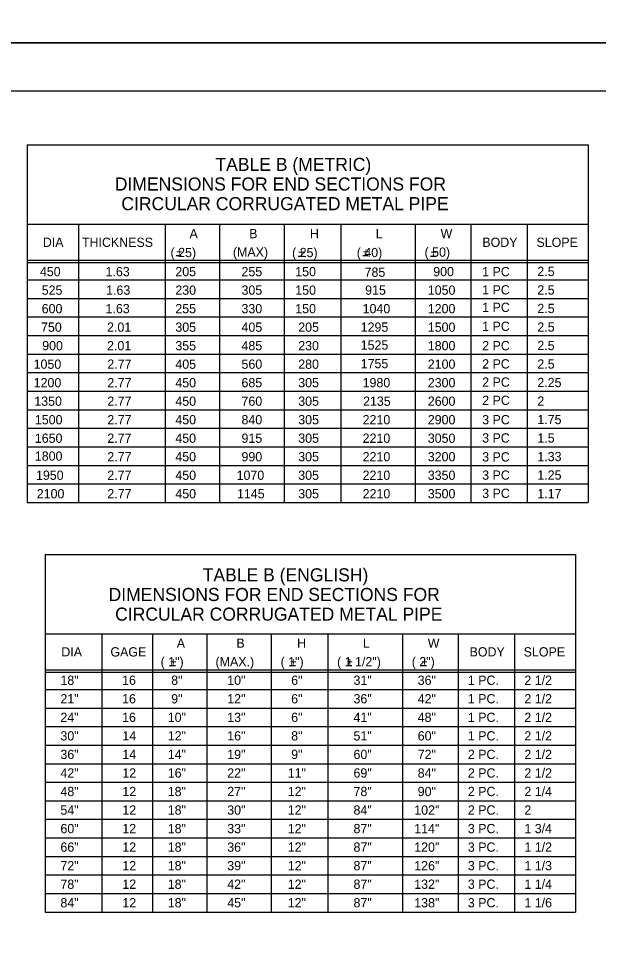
# Model space of a CAD drawing. Extents: x -17 to 888, y -473 to 715.
# Drawn here: x 265 to 444.9, y -161.9 to 128.4 of the extents above; entities that cross this region are included whole.
import ezdxf

# ---------------------------------------------------------------- set-up
doc = ezdxf.new("R2010")
doc.units = 0
for name, color, linetype in [('1', 7, 'Continuous'), ('2', 7, 'Continuous'), ('3', 7, 'Continuous'), ('PLT-BNDY', 7, 'Continuous')]:
    doc.layers.add(name, color=color, linetype=linetype)

msp = doc.modelspace()

# ---------------------------------------------------------------- linework, layer by layer
at = {"layer": '1'}
msp.add_lwpolyline([(808.79, -458.11), (808.79, 105.89), (22.79, 105.89), (22.79, -458.11), (808.79, -458.11), (808.79, -431.75), (608.79, -431.75), (608.79, -367.07), (808.79, -367.07), (808.79, -338.11), (608.79, -338.11), (608.79, -458.11), (687.6, -458.11), (687.6, -431.75), (687.6, -458.11), (764.6, -458.11), (764.6, -431.75), (764.6, -444.07), (808.79, -444.07)], dxfattribs=at)
at = {"layer": '2'}
for p, q in [((313.86, 54.8), (315.47, 54.8)), ((351.73, 54.67), (353.33, 54.67)), ((371.79, 54.8), (373.39, 54.8)), ((392.8, 54.67), (394.4, 54.67)), ((312.05, -72.55), (313.65, -72.55)), ((349.28, -72.55), (350.88, -72.55)), ((366.81, -72.55), (368.41, -72.55)), ((389.97, -72.55), (391.57, -72.55))]:
    msp.add_line(p, q, dxfattribs=at)
at = {"layer": '3'}
for p, q in [((267.68, 89.16), (267.68, -21.87)), ((267.68, 89.16), (441.73, 89.16)), ((441.73, 89.16), (441.73, -21.87)), ((267.68, 64.52), (441.73, 64.52)), ((277.2, 64.52), (294.77, 64.52)), ((283.61, 64.52), (283.61, -21.87)), ((294.77, 64.52), (310.45, 64.52)), ((310.45, 64.52), (310.45, -21.87)), ((327.35, 64.52), (327.35, -21.87)), ((347.35, 64.52), (347.35, -21.87)), ((364.92, 64.52), (364.92, -21.87)), ((388.03, 64.52), (388.03, -21.87)), ((405.34, 64.52), (405.34, -21.87)), ((405.34, 64.52), (422.77, 64.52)), ((422.77, 64.52), (422.77, -21.87)), ((422.77, 64.52), (441.73, 64.52)), ((441.73, 58.76), (441.73, 1.17)), ((267.68, 53.35), (441.73, 53.35)), ((267.68, 52.66), (441.73, 52.66)), ((267.68, 47.24), (441.73, 47.24)), ((267.68, 41.49), (441.73, 41.49)), ((267.68, 35.73), (441.73, 35.73)), ((267.68, 29.97), (441.73, 29.97)), ((267.68, 24.21), (441.73, 24.21)), ((267.68, 18.45), (441.73, 18.45)), ((267.68, 12.69), (441.73, 12.69)), ((267.68, 6.93), (441.73, 6.93)), ((267.68, 1.17), (441.73, 1.17)), ((267.68, -4.59), (441.73, -4.59)), ((267.68, -10.35), (441.73, -10.35)), ((267.68, -16.11), (441.73, -16.11)), ((267.68, -21.87), (441.73, -21.87)), ((277.2, -21.87), (277.2, -21.87)), ((273.23, -38.07), (273.23, -149.1)), ((273.23, -38.07), (437.77, -38.07)), ((437.77, -38.07), (437.77, -149.1)), ((273.23, -62.7), (437.77, -62.7)), ((273.23, -62.7), (273.23, -73.88)), ((273.23, -62.7), (290.8, -62.7)), ((290.8, -62.7), (290.8, -149.1)), ((290.8, -62.7), (306.48, -62.7)), ((306.48, -62.7), (306.48, -149.1)), ((323.38, -62.7), (323.38, -149.1)), ((343.38, -62.7), (343.38, -149.1)), ((360.95, -62.7), (360.95, -149.1)), ((384.07, -62.7), (384.07, -149.1)), ((401.37, -62.7), (401.37, -149.1)), ((401.37, -62.7), (418.81, -62.7)), ((418.81, -62.7), (418.81, -149.1)), ((418.81, -62.7), (437.77, -62.7)), ((437.77, -68.46), (437.77, -126.06)), ((273.23, -73.88), (437.77, -73.88)), ((273.23, -74.56), (437.77, -74.56)), ((273.23, -79.98), (437.77, -79.98)), ((273.23, -85.74), (437.77, -85.74)), ((273.23, -85.74), (273.23, -91.5)), ((273.23, -91.5), (437.77, -91.5)), ((273.23, -97.26), (437.77, -97.26)), ((273.23, -103.02), (437.77, -103.02)), ((273.23, -108.78), (437.77, -108.78)), ((273.23, -114.54), (437.77, -114.54)), ((273.23, -120.3), (437.77, -120.3)), ((273.23, -126.06), (437.77, -126.06)), ((273.23, -131.82), (437.77, -131.82)), ((273.23, -137.58), (437.77, -137.58)), ((273.23, -143.34), (437.77, -143.34)), ((273.23, -149.1), (437.77, -149.1)), ((273.23, -149.1), (273.23, -149.1)), ((437.77, -149.1), (437.77, -149.1))]:
    msp.add_line(p, q, dxfattribs=at)
at = {"layer": 'PLT-BNDY'}
for points in [[(-17.21, 714.89), (823.79, 714.89), (823.79, 120.89), (-17.21, 120.89)], [(-17.21, 120.89), (823.79, 120.89), (823.79, -473.11), (-17.21, -473.11)]]:
    msp.add_lwpolyline(points, close=True, dxfattribs=at)

# ---------------------------------------------------------------- texts
at = {"layer": '2'}
for p in [(313.86, 54.78), (351.72, 54.65), (371.78, 54.78), (392.79, 54.65), (312.04, -72.57), (349.27, -72.57), (366.8, -72.57), (389.96, -72.57)]:
    msp.add_text('+', height=2.47, dxfattribs=at).set_placement(p)
at = {"layer": '3'}
for s, height, p in [('TABLE B (METRIC)', 4.0685, (326.04, 81.1)), ('DIMENSIONS FOR END SECTIONS FOR', 4.0685, (294.82, 75)), ('CIRCULAR CORRUGATED METAL PIPE', 4.0682, (296.86, 68.9)), ('A', 2.88, (318.02, 60.2)), ('B', 2.88, (336.52, 60.2)), ('H', 2.88, (355.37, 60.2)), ('L', 2.88, (375.78, 60.2)), ('W', 2.88, (395.92, 60.2)), ('DIA', 2.88, (272.5, 57.5)), ('THICKNESS', 2.88, (284.64, 57.5)), ('BODY', 2.88, (408.87, 57.5)), ('SLOPE', 2.88, (425.67, 57.5)), ('( 25)', 2.88, (312.13, 54.32)), ('(MAX)', 2.88, (331.48, 54.44)), ('( 25)', 2.88, (349.84, 54.32)), ('( 40)', 2.88, (369.9, 54.32)), ('( 50)', 2.88, (390.94, 54.44)), ('450 ', 2.88, (271.6, 48.39)), ('1.63', 2.88, (291.96, 48.39)), ('205 ', 2.88, (313.62, 48.39)), ('255 ', 2.88, (334.14, 48.39)), ('150 ', 2.88, (350.83, 48.39)), ('785 ', 2.88, (372.33, 48.21)), ('900 ', 2.88, (393.64, 48.39)), ('1 PC ', 2.88, (408.83, 48.39)), ('2.5  ', 2.88, (425.94, 48.44)), ('525 ', 2.88, (272.15, 42.64)), ('1.63', 2.88, (292.14, 42.64)), ('230 ', 2.88, (313.62, 42.64)), ('305 ', 2.88, (334.14, 42.64)), ('150 ', 2.88, (350.83, 42.64)), ('915 ', 2.88, (372.51, 42.64)), ('1050', 2.88, (391.95, 42.64)), ('1 PC ', 2.88, (408.83, 42.73)), ('2.5  ', 2.88, (425.94, 42.69)), ('600 ', 2.88, (272.15, 36.89)), ('1.63', 2.88, (291.96, 36.89)), ('255 ', 2.88, (313.62, 36.89)), ('330 ', 2.88, (334.14, 36.89)), ('150 ', 2.88, (350.83, 36.89)), ('1040', 2.88, (371.73, 36.89)), ('1200', 2.88, (391.95, 36.89)), ('1 PC ', 2.88, (408.83, 37.3)), ('2.5  ', 2.88, (425.94, 36.94)), ('750 ', 2.88, (271.94, 31.14)), ('2.01', 2.88, (292.43, 31.14)), ('305 ', 2.88, (313.62, 31.14)), ('405 ', 2.88, (334.14, 31.14)), ('205 ', 2.88, (351.75, 31.14)), ('1295', 2.88, (371.13, 31.14)), ('1500', 2.88, (391.95, 31.14)), ('1 PC ', 2.88, (408.83, 31.41)), ('2.5  ', 2.88, (425.94, 31.19)), ('900 ', 2.88, (272.31, 25.39)), ('2.01', 2.88, (292.43, 25.39)), ('355 ', 2.88, (313.62, 25.39)), ('485 ', 2.88, (334.14, 25.39)), ('230 ', 2.88, (351.75, 25.39)), ('1525', 2.88, (371.13, 25.57)), ('1800', 2.88, (391.95, 25.39)), ('2 PC ', 2.88, (408.83, 25.39)), ('2.5  ', 2.88, (425.94, 25.44)), ('1050', 2.88, (269.64, 19.64)), ('2.77', 2.88, (292.51, 19.64)), ('405 ', 2.88, (313.62, 19.64)), ('560 ', 2.88, (334.14, 19.64)), ('280 ', 2.88, (351.75, 19.64)), ('1755', 2.88, (371.13, 19.82)), ('2100', 2.88, (391.95, 19.64)), ('2 PC ', 2.88, (408.83, 19.73)), ('2.5  ', 2.88, (425.94, 19.69)), ('1200', 2.88, (269.66, 13.89)), ('2.77', 2.88, (292.51, 13.89)), ('450 ', 2.88, (313.62, 13.89)), ('685 ', 2.88, (334.14, 13.89)), ('305 ', 2.88, (351.75, 13.89)), ('1980', 2.88, (371.73, 13.89)), ('2300', 2.88, (391.95, 13.89)), ('2 PC ', 2.88, (408.83, 14.07)), ('2.25 ', 2.88, (425.94, 13.94)), ('1350', 2.88, (269.85, 8.14)), ('2.77', 2.88, (292.51, 8.14)), ('450 ', 2.88, (313.62, 8.14)), ('760 ', 2.88, (334.14, 8.14)), ('305 ', 2.88, (351.75, 8.14)), ('2135', 2.88, (371.86, 8.14)), ('2600', 2.88, (391.95, 8.14)), ('2 PC ', 2.88, (408.83, 8.41)), ('2    ', 2.88, (425.94, 8.19)), ('1500', 2.88, (270.03, 2.39)), ('2.77', 2.88, (292.51, 2.39)), ('450 ', 2.88, (313.62, 2.39)), ('840 ', 2.88, (334.14, 2.39)), ('305 ', 2.88, (351.75, 2.39)), ('2210', 2.88, (371.73, 2.39)), ('2900', 2.88, (391.95, 2.39)), ('3 PC ', 2.88, (408.83, 2.39)), ('1.75 ', 2.88, (425.94, 2.44)), ('1650', 2.88, (270.02, -3.36)), ('2.77', 2.88, (292.51, -3.36)), ('450 ', 2.88, (313.62, -3.36)), ('915 ', 2.88, (334.14, -3.36)), ('305 ', 2.88, (351.75, -3.36)), ('2210', 2.88, (371.73, -3.36)), ('3050', 2.88, (391.95, -3.36)), ('3 PC ', 2.88, (408.83, -3.27)), ('1.5  ', 2.88, (425.94, -3.31)), ('1800', 2.88, (270.02, -8.92)), ('2.77', 2.88, (292.51, -9.11)), ('450 ', 2.88, (313.62, -9.11)), ('990 ', 2.88, (334.14, -9.11)), ('305 ', 2.88, (351.75, -9.11)), ('2210', 2.88, (371.73, -9.11)), ('3200', 2.88, (391.95, -9.11)), ('3 PC ', 2.88, (408.83, -9.16)), ('1.33 ', 2.88, (425.94, -9.06)), ('1950', 2.88, (270.38, -14.86)), ('2.77', 2.88, (292.51, -14.86)), ('450 ', 2.88, (313.62, -14.86)), ('1070', 2.88, (332.63, -14.86)), ('305 ', 2.88, (351.75, -14.86)), ('2210', 2.88, (371.73, -14.86)), ('3350', 2.88, (391.95, -14.86)), ('3 PC ', 2.88, (408.83, -14.82)), ('1.25 ', 2.88, (425.94, -14.81)), ('2100', 2.88, (270.62, -20.61)), ('2.77', 2.88, (292.51, -20.61)), ('450 ', 2.88, (313.62, -20.61)), ('1145', 2.88, (332.75, -20.61)), ('305 ', 2.88, (351.75, -20.61)), ('2210', 2.88, (371.73, -20.61)), ('3500', 2.88, (391.95, -20.61)), ('3 PC ', 2.88, (408.83, -20.48)), ('1.17 ', 2.88, (425.94, -20.56)), ('TABLE B (ENGLISH)', 4.0685, (322.1, -46.4)), ('DIMENSIONS FOR END SECTIONS FOR', 4.0685, (292.9, -52.5)), ('CIRCULAR CORRUGATED METAL PIPE', 4.0682, (294.93, -58.6)), ('A', 2.88, (314.05, -67.02)), ('B', 2.88, (332.56, -67.02)), ('H', 2.88, (351.4, -67.02)), ('L', 2.88, (371.82, -67.02)), ('W', 2.88, (391.95, -67.02)), ('DIA', 2.88, (278.23, -69.73)), ('GAGE', 2.88, (293.48, -69.73)), ('BODY', 2.88, (404.91, -69.73)), ('SLOPE', 2.88, (421.7, -69.73)), ('( 1")', 2.88, (309.05, -72.78)), ('(MAX.)', 2.88, (326.08, -72.78)), ('( 1")', 2.88, (346.28, -72.78)), ('( 1 1/2")', 2.88, (363.81, -72.78)), ('( 2")', 2.88, (386.97, -72.78)), ('18"', 2.88, (277.96, -78.54)), ('16', 2.88, (297.09, -78.54)), (' 8"', 2.88, (311.26, -78.54)), ('10"', 2.88, (329.72, -78.54)), (' 6"', 2.88, (348.49, -78.54)), ('31"', 2.88, (368.9, -78.54)), (' 36"', 2.88, (387.75, -78.54)), ('1 PC.', 2.88, (404.38, -78.54)), ('2 1/2', 2.88, (421.92, -78.54)), ('2 1/2', 2.88, (421.92, -84.3)), ('21"', 2.88, (277.96, -84.3)), ('16', 2.88, (297.09, -84.3)), (' 9"', 2.88, (311.26, -84.3)), ('12"', 2.88, (329.72, -84.3)), (' 6"', 2.88, (348.49, -84.3)), ('36"', 2.88, (368.9, -84.3)), (' 42"', 2.88, (387.75, -84.3)), ('1 PC.', 2.88, (404.38, -84.3)), ('2 1/2', 2.88, (421.92, -90.06)), ('24"', 2.88, (277.96, -90.06)), ('16', 2.88, (297.09, -90.06)), ('10"', 2.88, (311.26, -90.06)), ('13"', 2.88, (329.72, -90.06)), (' 6"', 2.88, (348.49, -90.06)), ('41"', 2.88, (368.9, -90.06)), (' 48"', 2.88, (387.75, -90.06)), ('1 PC.', 2.88, (404.38, -90.06)), ('30"', 2.88, (277.96, -95.82)), ('12"', 2.88, (311.26, -95.82)), ('16"', 2.88, (329.72, -95.82)), (' 8"', 2.88, (348.49, -95.82)), (' 60"', 2.88, (387.75, -95.82)), ('1 PC.', 2.88, (404.38, -95.82)), ('2 1/2', 2.88, (421.92, -95.82)), ('14', 2.88, (297.17, -95.82)), ('51"', 2.88, (368.9, -95.82)), ('36"', 2.88, (277.96, -101.58)), ('14', 2.88, (297.17, -101.58)), ('14"', 2.88, (311.26, -101.58)), ('19"', 2.88, (329.72, -101.58)), (' 9"', 2.88, (348.49, -101.58)), ('60"', 2.88, (368.9, -101.58)), (' 72"', 2.88, (387.75, -101.58)), ('2 PC.', 2.88, (404.38, -101.58)), ('2 1/2', 2.88, (421.92, -101.58)), ('42"', 2.88, (277.96, -107.34)), ('12', 2.88, (297.17, -107.34)), ('16"', 2.88, (311.26, -107.34)), ('22"', 2.88, (329.72, -107.34)), ('11"', 2.88, (348.49, -107.34)), ('69"', 2.88, (368.9, -107.34)), (' 84"', 2.88, (387.75, -107.34)), ('2 PC.', 2.88, (404.38, -107.34)), ('2 1/2', 2.88, (421.92, -107.34)), ('48"', 2.88, (277.96, -113.1)), ('12', 2.88, (297.17, -113.1)), ('18"', 2.88, (311.26, -113.1)), ('27"', 2.88, (329.72, -113.1)), ('12"', 2.88, (348.49, -113.1)), ('78"', 2.88, (368.9, -113.1)), (' 90"', 2.88, (387.75, -113.1)), ('2 PC.', 2.88, (404.38, -113.1)), ('2 1/4', 2.88, (421.92, -113.1)), ('54"', 2.88, (277.96, -118.86)), ('12', 2.88, (297.17, -118.86)), ('18"', 2.88, (311.26, -118.86)), ('30"', 2.88, (329.72, -118.86)), ('12"', 2.88, (348.49, -118.86)), ('84"', 2.88, (368.9, -118.86)), ('102"', 2.88, (387.75, -118.86)), ('2 PC.', 2.88, (404.38, -118.86)), ('2', 2.88, (421.92, -118.86)), ('60"', 2.88, (277.96, -124.62)), ('12', 2.88, (297.17, -124.62)), ('18"', 2.88, (311.26, -124.62)), ('33"', 2.88, (329.72, -124.62)), ('12"', 2.88, (348.49, -124.62)), ('87"', 2.88, (368.9, -124.62)), ('114"', 2.88, (387.75, -124.62)), ('3 PC.', 2.88, (404.38, -124.62)), ('1 3/4', 2.88, (421.92, -124.62)), ('66"', 2.88, (277.96, -130.38)), ('12', 2.88, (297.17, -130.38)), ('18"', 2.88, (311.26, -130.38)), ('36"', 2.88, (329.72, -130.38)), ('12"', 2.88, (348.49, -130.38)), ('87"', 2.88, (368.9, -130.38)), ('120"', 2.88, (387.75, -130.38)), ('3 PC.', 2.88, (404.38, -130.38)), ('1 1/2', 2.88, (421.92, -130.38)), ('72"', 2.88, (277.96, -136.14)), ('12', 2.88, (297.17, -136.14)), ('18"', 2.88, (311.26, -136.14)), ('39"', 2.88, (329.72, -136.14)), ('12"', 2.88, (348.49, -136.14)), ('87"', 2.88, (368.9, -136.14)), ('126"', 2.88, (387.75, -136.14)), ('3 PC.', 2.88, (404.38, -136.14)), ('1 1/3', 2.88, (421.92, -136.14)), ('78"', 2.88, (277.96, -141.9)), ('12', 2.88, (297.17, -141.9)), ('18"', 2.88, (311.26, -141.9)), ('42"', 2.88, (329.72, -141.9)), ('12"', 2.88, (348.49, -141.9)), ('87"', 2.88, (368.9, -141.9)), ('132"', 2.88, (387.75, -141.9)), ('3 PC.', 2.88, (404.38, -141.9)), ('1 1/4', 2.88, (421.92, -141.9)), ('84"', 2.88, (277.96, -147.66)), ('12', 2.88, (297.17, -147.66)), ('18"', 2.88, (311.26, -147.66)), ('45"', 2.88, (329.72, -147.66)), ('12"', 2.88, (348.49, -147.66)), ('87"', 2.88, (368.9, -147.66)), ('138"', 2.88, (387.75, -147.66)), ('3 PC.', 2.88, (404.38, -147.66)), ('1 1/6', 2.88, (421.92, -147.66))]:
    msp.add_text(s, height=height, dxfattribs=at).set_placement(p)

doc.saveas('drawing.dxf')
